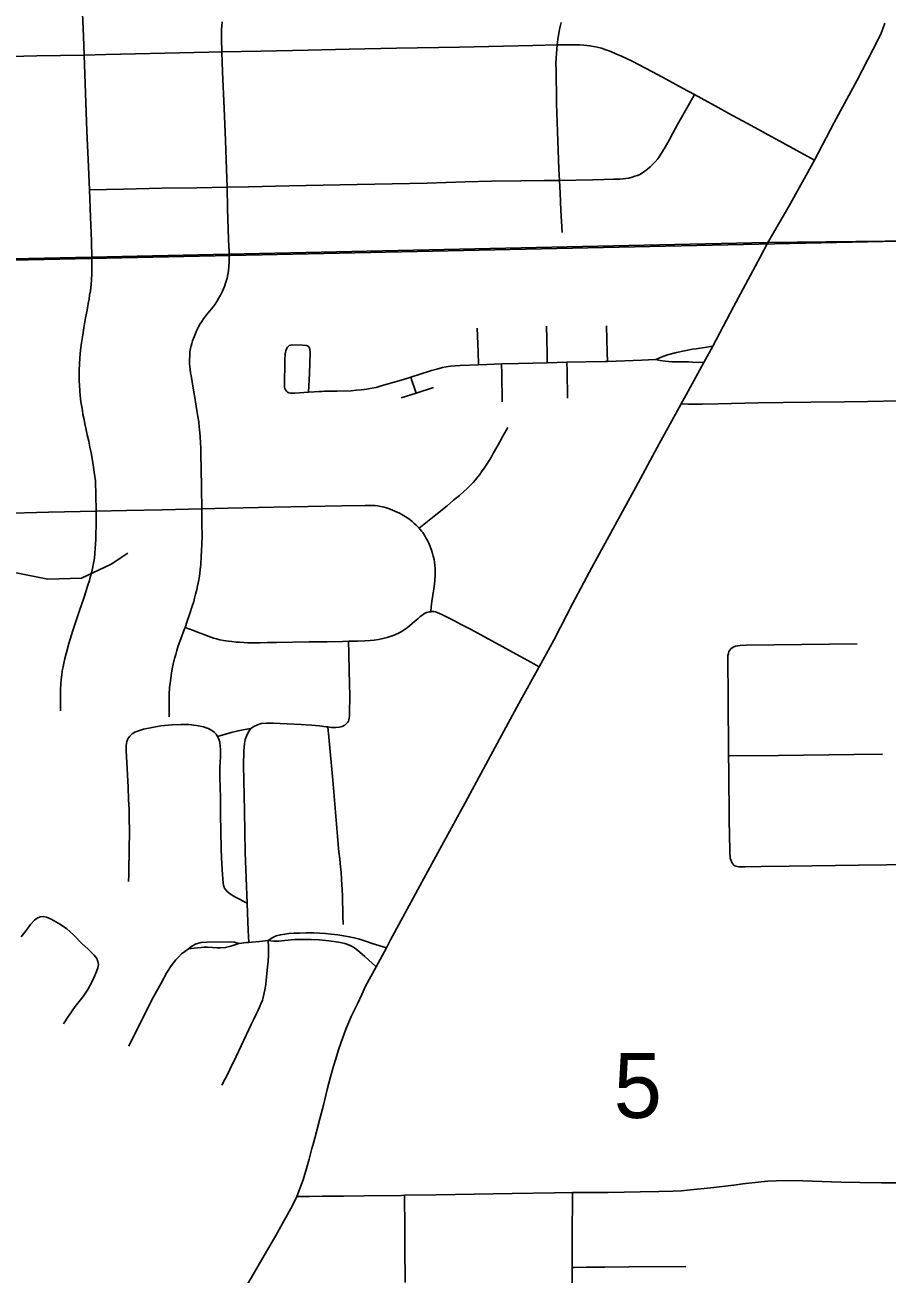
# Model space of a CAD drawing. Extents: x -6.4 to 34, y -4.2 to 22.
# Drawn here: x 4.993 to 5.548, y 15.21 to 16.015 of the extents above; entities that cross this region are included whole.
import ezdxf

# ---------------------------------------------------------------- set-up
doc = ezdxf.new("R2010")
doc.units = 0
for name, color, linetype in [('GM_X_City_Street', 7, 'Continuous'), ('GM_X_Corporation', 7, 'Continuous'), ('GM_X_County_Road', 7, 'Continuous'), ('GM_X_Minor_River', 7, 'Continuous'), ('GM_X_Section_Text', 7, 'Continuous'), ('GM_X_State_Route', 7, 'Continuous')]:
    doc.layers.add(name, color=color, linetype=linetype)

msp = doc.modelspace()

# ---------------------------------------------------------------- linework, layer by layer
at = {"layer": 'GM_X_City_Street'}
msp.add_line((5.24472, 15.77786), (5.25605, 15.78143), dxfattribs=at)
for points in [[(5.01565, 15.57307), (5.01549, 15.57751), (5.01549, 15.58072), (5.01566, 15.58713), (5.01582, 15.59025), (5.01607, 15.5933), (5.0164, 15.59634), (5.01674, 15.59889), (5.01723, 15.60144), (5.01773, 15.6039), (5.01838, 15.60686), (5.01937, 15.61073), (5.02103, 15.61641), (5.0235, 15.62479), (5.02754, 15.63704), (5.03075, 15.64633), (5.0333, 15.65414), (5.03422, 15.65708), (5.03479, 15.65916), (5.03555, 15.6621), (5.03619, 15.66492), (5.03693, 15.66829), (5.03743, 15.67158), (5.03776, 15.67462), (5.03801, 15.67766), (5.03818, 15.68071), (5.03826, 15.68358), (5.03834, 15.68605), (5.03851, 15.69329), (5.03852, 15.7017), (5.03852, 15.70447), (5.03844, 15.70982), (5.03828, 15.71467), (5.0382, 15.71837), (5.03804, 15.72125), (5.03779, 15.72405), (5.03739, 15.72693), (5.03693, 15.73017), (5.03645, 15.73283), (5.03591, 15.73581), (5.03525, 15.73926), (5.03452, 15.74305), (5.03378, 15.74691), (5.03288, 15.75103), (5.03196, 15.7552), (5.03137, 15.75797), (5.03074, 15.76081), (5.03009, 15.76411), (5.02968, 15.76657), (5.02927, 15.76896), (5.02878, 15.77217), (5.02829, 15.77636), (5.02805, 15.77932), (5.0278, 15.78294), (5.02764, 15.78557), (5.02764, 15.78853), (5.02769, 15.79252), (5.02791, 15.79652), (5.02814, 15.80054), (5.02856, 15.80556), (5.02913, 15.81024), (5.02988, 15.81543), (5.03062, 15.81995), (5.03169, 15.82636), (5.03268, 15.83138), (5.03351, 15.83558), (5.03401, 15.83845), (5.03438, 15.84091), (5.03483, 15.8438), (5.03533, 15.84782), (5.03554, 15.85089), (5.03575, 15.85481), (5.03583, 15.85893), (5.03575, 15.86477), (5.0356, 15.87587), (5.03503, 15.89125), (5.03433, 15.90873), (5.03373, 15.92356), (5.03251, 15.9466), (5.03171, 15.97103), (5.03079, 15.99559), (5.03034, 16.00788), (5.02928, 16.03246)], [(5.0856, 15.56931), (5.0856, 15.57252), (5.08557, 15.5768), (5.08553, 15.58058), (5.08561, 15.58371), (5.08586, 15.58823), (5.08619, 15.59102), (5.0866, 15.59415), (5.0871, 15.59736), (5.0876, 15.60024), (5.08826, 15.6032), (5.08908, 15.60673), (5.08982, 15.60952), (5.09056, 15.61199), (5.09145, 15.61491), (5.09304, 15.61956), (5.09551, 15.62589), (5.09585, 15.62684), (5.0973, 15.63088), (5.09905, 15.63576), (5.10054, 15.64045), (5.10144, 15.64349), (5.10204, 15.64579), (5.10268, 15.64826), (5.10343, 15.6513), (5.10395, 15.65366), (5.10449, 15.65648), (5.10515, 15.65985), (5.10565, 15.66405), (5.10599, 15.66766), (5.10631, 15.67227), (5.10648, 15.67638), (5.10665, 15.68017), (5.10682, 15.68617), (5.10674, 15.693), (5.10661, 15.70335), (5.10643, 15.71668), (5.10619, 15.72968), (5.10603, 15.73774), (5.10595, 15.74226), (5.10579, 15.74571), (5.10563, 15.74966), (5.10543, 15.75238), (5.10506, 15.75591), (5.10465, 15.75928), (5.10416, 15.76266), (5.10351, 15.7667), (5.10285, 15.7708), (5.10211, 15.77507), (5.10162, 15.77837), (5.10114, 15.78123), (5.10068, 15.78364), (5.10014, 15.78667), (5.09973, 15.78889), (5.09942, 15.79099), (5.09908, 15.79325), (5.09883, 15.79663), (5.09883, 15.79926), (5.09884, 15.80213), (5.099, 15.80452), (5.09934, 15.80658), (5.09975, 15.8083), (5.10017, 15.80973), (5.10073, 15.81159), (5.10164, 15.81406), (5.10255, 15.8162), (5.10354, 15.81841), (5.10461, 15.82047), (5.10568, 15.82237), (5.10664, 15.82389), (5.10782, 15.82573), (5.10979, 15.82836), (5.11185, 15.83091), (5.11391, 15.83338), (5.11523, 15.83518), (5.11638, 15.83691), (5.11745, 15.83872), (5.11869, 15.84086), (5.12, 15.84357), (5.12126, 15.84657), (5.12215, 15.84941), (5.12292, 15.852), (5.12346, 15.85434), (5.12387, 15.85665), (5.12412, 15.85952), (5.12421, 15.86216), (5.12424, 15.8668), (5.12422, 15.8689), (5.12397, 15.87688), (5.12325, 15.8967), (5.12297, 15.9105), (5.12261, 15.9222), (5.12196, 15.9407), (5.12115, 15.96143), (5.12002, 15.98462), (5.11959, 15.99774), (5.11951, 16.00018), (5.1194, 16.00379), (5.1193, 16.00757), (5.1193, 16.01011), (5.11938, 16.01209), (5.11954, 16.01447), (5.11987, 16.01702)], [(5.33883, 15.88123), (5.3381, 15.89571), (5.33756, 15.90657), (5.33715, 15.91492), (5.3368, 15.92211), (5.336, 15.94637), (5.33535, 15.96455), (5.33522, 15.97179), (5.33506, 15.98009), (5.33495, 15.98585), (5.33487, 15.99046), (5.33504, 15.99367), (5.33521, 15.99662), (5.33546, 15.99951), (5.33579, 16.00229), (5.33622, 16.00579), (5.33686, 16.00978), (5.33744, 16.01316), (5.33818, 16.01669)], [(4.97509, 15.99452), (5.00033, 15.99508), (5.03079, 15.99559), (5.04483, 15.99596), (5.07337, 15.99668), (5.11128, 15.99755), (5.11959, 15.99774), (5.14476, 15.99827), (5.17527, 15.99891), (5.20159, 15.99947), (5.23218, 16.00002), (5.27264, 16.00074), (5.31994, 16.00185), (5.33579, 16.00229), (5.34034, 16.00233), (5.34453, 16.00233), (5.3479, 16.00233), (5.35028, 16.00225), (5.35292, 16.00208), (5.35481, 16.00191), (5.35662, 16.00166), (5.35908, 16.00125), (5.36139, 16.00076), (5.36418, 16.00002), (5.36698, 15.99911), (5.37035, 15.99787), (5.37355, 15.99655), (5.37709, 15.99499), (5.38038, 15.99342), (5.38392, 15.9917), (5.38852, 15.9893), (5.39262, 15.98715), (5.39666, 15.98502), (5.40357, 15.98132), (5.41646, 15.97438), (5.42417, 15.97023), (5.43953, 15.96182), (5.44878, 15.95678), (5.45832, 15.95159), (5.48109, 15.93907), (5.50152, 15.92799)], [(5.03433, 15.90873), (5.05618, 15.90923), (5.08085, 15.90979), (5.10347, 15.9101), (5.12297, 15.9105), (5.13677, 15.91082), (5.16301, 15.91146), (5.20685, 15.91233), (5.25192, 15.91321), (5.27643, 15.91393), (5.29337, 15.91433), (5.31229, 15.91456), (5.32726, 15.9148), (5.33715, 15.91492), (5.35842, 15.91536), (5.36607, 15.91552), (5.37191, 15.9156), (5.37389, 15.91567), (5.37611, 15.91576), (5.37816, 15.91592), (5.37989, 15.91608), (5.38178, 15.91641), (5.384, 15.91698), (5.38581, 15.91756), (5.38738, 15.91813), (5.38886, 15.91879), (5.39067, 15.91978), (5.39223, 15.92076), (5.39396, 15.92208), (5.39569, 15.92356), (5.39741, 15.92528), (5.39881, 15.92676), (5.40046, 15.92882), (5.40194, 15.93079), (5.40367, 15.9335), (5.40532, 15.9363), (5.40789, 15.94089), (5.41026, 15.94534), (5.4133, 15.95093), (5.4166, 15.95693), (5.42002, 15.96294), (5.42417, 15.97023)], [(5.28492, 15.79608), (5.28467, 15.80436), (5.28423, 15.81959)], [(5.32932, 15.79737), (5.32925, 15.80307), (5.32907, 15.8127), (5.32891, 15.82097)], [(5.3681, 15.79829), (5.36796, 15.80392), (5.36756, 15.82128)], [(5.1755, 15.77849), (5.17614, 15.7904), (5.17637, 15.79704), (5.17644, 15.8043), (5.17633, 15.80596), (5.17611, 15.80703), (5.1757, 15.80772), (5.17511, 15.80816), (5.17404, 15.8085), (5.1715, 15.80873), (5.16485, 15.8089), (5.16383, 15.80879), (5.16293, 15.80848), (5.16226, 15.80797), (5.16186, 15.80748), (5.16145, 15.80673), (5.16107, 15.80581), (5.16085, 15.80506), (5.16067, 15.80418), (5.16044, 15.80315), (5.16029, 15.80195), (5.16019, 15.80067), (5.16013, 15.79913), (5.15986, 15.78236), (5.16003, 15.78158), (5.16027, 15.78086), (5.16065, 15.78005), (5.16127, 15.77904), (5.16196, 15.77844), (5.16275, 15.77807), (5.16377, 15.77784), (5.16469, 15.77786), (5.16668, 15.7779), (5.1755, 15.77849), (5.17909, 15.77873), (5.18216, 15.77888), (5.18391, 15.77896), (5.18584, 15.77904), (5.18755, 15.77906), (5.19399, 15.77911), (5.20294, 15.77935), (5.2062, 15.77966), (5.20967, 15.77998), (5.21295, 15.78048), (5.21632, 15.781), (5.21898, 15.78155), (5.2217, 15.78225), (5.23885, 15.78727), (5.24146, 15.7881), (5.25474, 15.79234), (5.25819, 15.79329), (5.26187, 15.7943), (5.26423, 15.79478), (5.26686, 15.79521), (5.26993, 15.79552), (5.27309, 15.79568), (5.28492, 15.79608), (5.29027, 15.79632), (5.29991, 15.79662), (5.3107, 15.79695), (5.32932, 15.79737), (5.34189, 15.79767), (5.36658, 15.79824), (5.3681, 15.79829), (5.39036, 15.79911), (5.39452, 15.79923), (5.39931, 15.7996)], [(5.39931, 15.7996), (5.40262, 15.80101), (5.40673, 15.80254), (5.41256, 15.80407), (5.4229, 15.8061), (5.42536, 15.80647), (5.43593, 15.80807)], [(5.39931, 15.7996), (5.40207, 15.79892), (5.40526, 15.79843), (5.40961, 15.79806), (5.42041, 15.79789), (5.42292, 15.79781), (5.43022, 15.79757)], [(5.30015, 15.7722), (5.29996, 15.79028), (5.29991, 15.79662)], [(5.34242, 15.77456), (5.34206, 15.79227), (5.34189, 15.79767)], [(5.23511, 15.77475), (5.24472, 15.77786), (5.2441, 15.77983), (5.24211, 15.78607), (5.24146, 15.7881)], [(5.41565, 15.77091), (5.42027, 15.77079), (5.42921, 15.77079), (5.43953, 15.77095), (5.46531, 15.77149), (5.48145, 15.77178), (5.49916, 15.77199), (5.52087, 15.77228), (5.53592, 15.77249), (5.55581, 15.77285), (5.56907, 15.77309), (5.58833, 15.77348), (5.60188, 15.77376), (5.61778, 15.77409), (5.65055, 15.77489), (5.66469, 15.77524), (5.68108, 15.77557)], [(5.24668, 15.69082), (5.24998, 15.69336), (5.25754, 15.69944), (5.26478, 15.70527), (5.26896, 15.70875), (5.27269, 15.71185), (5.27556, 15.7144), (5.27771, 15.71645), (5.28001, 15.71867), (5.28157, 15.72031), (5.28315, 15.72205), (5.28462, 15.72385), (5.28589, 15.72546), (5.28701, 15.72705), (5.28866, 15.72943), (5.29038, 15.73207), (5.29186, 15.73445), (5.29327, 15.73675), (5.29475, 15.7393), (5.2968, 15.743), (5.29842, 15.74597), (5.30067, 15.75007), (5.3038, 15.75566)], [(4.9768, 15.70032), (5.00788, 15.70104), (5.03852, 15.7017), (5.05805, 15.70216), (5.08108, 15.70272), (5.10661, 15.70335), (5.12335, 15.70376), (5.15305, 15.7044), (5.17517, 15.70488), (5.1968, 15.70527), (5.21193, 15.70542), (5.21449, 15.70546), (5.2167, 15.70542), (5.21835, 15.70534), (5.21981, 15.70516), (5.2209, 15.70501), (5.22213, 15.70476), (5.2241, 15.70426), (5.22567, 15.70385), (5.22697, 15.70342), (5.22813, 15.70303), (5.22953, 15.70245), (5.23109, 15.70176), (5.23249, 15.70114), (5.23397, 15.70039), (5.23553, 15.69957), (5.23767, 15.69833), (5.23948, 15.69718), (5.24096, 15.69611), (5.24219, 15.69512), (5.24359, 15.69389), (5.24482, 15.69274), (5.24597, 15.69159), (5.24668, 15.69082), (5.24734, 15.68999), (5.24816, 15.68891), (5.24901, 15.68796), (5.25008, 15.6864), (5.25115, 15.68459), (5.25213, 15.68278), (5.25293, 15.68109), (5.25383, 15.67896), (5.25468, 15.67661), (5.25534, 15.67447), (5.25583, 15.67283), (5.25632, 15.67069), (5.25665, 15.66888), (5.25681, 15.66707), (5.25697, 15.66485), (5.25705, 15.66246), (5.25697, 15.66033), (5.2568, 15.65761), (5.25656, 15.65481), (5.25614, 15.65169), (5.25556, 15.64766), (5.25498, 15.64355), (5.25449, 15.64017), (5.25416, 15.63693)], [(5.09585, 15.62684), (5.10062, 15.62504), (5.10563, 15.62314), (5.10924, 15.6218), (5.11188, 15.62084), (5.11443, 15.62001), (5.1162, 15.61951), (5.11838, 15.61894), (5.1206, 15.61844), (5.12208, 15.6182), (5.12389, 15.61795), (5.12611, 15.6177), (5.12874, 15.61745), (5.13097, 15.61731), (5.13384, 15.61712), (5.13614, 15.61703), (5.1395, 15.61692), (5.14428, 15.61695), (5.14897, 15.61705), (5.15473, 15.61719), (5.1757, 15.6175), (5.18746, 15.61766), (5.19741, 15.61782), (5.2012, 15.61791), (5.20695, 15.61805), (5.2118, 15.61821), (5.2151, 15.61838), (5.21765, 15.61862), (5.22044, 15.61904), (5.22341, 15.61969), (5.22603, 15.62043), (5.22877, 15.62132), (5.23053, 15.62194), (5.23184, 15.62251), (5.23341, 15.62325), (5.23509, 15.62412), (5.23706, 15.62527), (5.23895, 15.62658), (5.2406, 15.6279), (5.24216, 15.62931), (5.24369, 15.63064), (5.24583, 15.63246), (5.24743, 15.63382), (5.2485, 15.63464), (5.24957, 15.63538), (5.25055, 15.63595), (5.25154, 15.63637), (5.25261, 15.63669), (5.2535, 15.63689), (5.25416, 15.63693), (5.25483, 15.63702), (5.25623, 15.63702), (5.25719, 15.63689), (5.25845, 15.63653), (5.25993, 15.63587), (5.26174, 15.63504), (5.26478, 15.63356), (5.26906, 15.63134), (5.27389, 15.62883), (5.27983, 15.62574), (5.31871, 15.60449), (5.32416, 15.60151)], [(5.20195, 15.57189), (5.20197, 15.58264), (5.2016, 15.5989), (5.20133, 15.61027), (5.2012, 15.61791)], [(5.44765, 15.61298), (5.44921, 15.61408), (5.45056, 15.6147), (5.45205, 15.61506), (5.4537, 15.61524), (5.45748, 15.61533), (5.52896, 15.61627)], [(5.44765, 15.61298), (5.44643, 15.61139), (5.44605, 15.61015), (5.44577, 15.60873), (5.44565, 15.60699), (5.44562, 15.60531), (5.44583, 15.58301), (5.4462, 15.54402), (5.44629, 15.53456), (5.4466, 15.50276), (5.44694, 15.48325), (5.44706, 15.48083), (5.44714, 15.47933), (5.44728, 15.47824), (5.44756, 15.47705), (5.44799, 15.47593), (5.44855, 15.47501), (5.44893, 15.47444), (5.44958, 15.47375), (5.45024, 15.47332), (5.45094, 15.47301), (5.45173, 15.47278), (5.45285, 15.47265), (5.45677, 15.47268), (5.46719, 15.47274), (5.48518, 15.47294), (5.52985, 15.47357), (5.56605, 15.47407)], [(5.13703, 15.42389), (5.13664, 15.43157), (5.13606, 15.44289), (5.13581, 15.44926), (5.13454, 15.48181), (5.13407, 15.50854), (5.13346, 15.53837), (5.13364, 15.54711), (5.13411, 15.55208), (5.13467, 15.5547), (5.13546, 15.55685), (5.13674, 15.55962), (5.13825, 15.56163), (5.14012, 15.56307), (5.14245, 15.56419), (5.14486, 15.56488), (5.14832, 15.56514), (5.15255, 15.56514), (5.17076, 15.56424), (5.17385, 15.56412), (5.17756, 15.56388), (5.17992, 15.56366), (5.18253, 15.56342), (5.18674, 15.56287), (5.18796, 15.5627), (5.19033, 15.56247), (5.19303, 15.56235), (5.19531, 15.56252), (5.19718, 15.56305), (5.19876, 15.56387), (5.19999, 15.56486), (5.20058, 15.56558), (5.20114, 15.56636), (5.20151, 15.56724), (5.20174, 15.56849), (5.20184, 15.56988), (5.20195, 15.57189)], [(5.05945, 15.46311), (5.05961, 15.46746), (5.05971, 15.4705), (5.05999, 15.49593), (5.05989, 15.50347), (5.05981, 15.50955), (5.05952, 15.51607), (5.05917, 15.52401), (5.05881, 15.53188), (5.05782, 15.54748), (5.05792, 15.55073), (5.05844, 15.55331), (5.05903, 15.5551), (5.06031, 15.55684), (5.06182, 15.55819), (5.06352, 15.55929), (5.06658, 15.56049), (5.06914, 15.56131), (5.07458, 15.56243), (5.08028, 15.56337), (5.08757, 15.5641), (5.09323, 15.56439), (5.09829, 15.56423), (5.10332, 15.56366), (5.10773, 15.56283), (5.11084, 15.56181), (5.11258, 15.56092), (5.11472, 15.55936), (5.11593, 15.55817), (5.11678, 15.55662), (5.11757, 15.5548), (5.11818, 15.55298), (5.11859, 15.55045), (5.11866, 15.54815), (5.11874, 15.54595), (5.11862, 15.54341), (5.11846, 15.54003), (5.11833, 15.53709), (5.11819, 15.53415), (5.11825, 15.53149), (5.11832, 15.5286), (5.11851, 15.52562), (5.11851, 15.52237), (5.11864, 15.51863), (5.11876, 15.50619), (5.11893, 15.49556), (5.11919, 15.48437), (5.11943, 15.47814), (5.11954, 15.47503), (5.11978, 15.4707), (5.12035, 15.46214), (5.12062, 15.46069), (5.12131, 15.45891), (5.12256, 15.45706), (5.12428, 15.45553), (5.1264, 15.45403), (5.12839, 15.45302), (5.13581, 15.44926)], [(5.11678, 15.55662), (5.12557, 15.55908), (5.13001, 15.56032), (5.13433, 15.56101), (5.13825, 15.56163)], [(5.19779, 15.43535), (5.1976, 15.44122), (5.19723, 15.45373), (5.19711, 15.45796), (5.19672, 15.46443), (5.19644, 15.4691), (5.19607, 15.47266), (5.19556, 15.47756), (5.19507, 15.48222), (5.19458, 15.48698), (5.19413, 15.49242), (5.19119, 15.52838), (5.18858, 15.55616), (5.18796, 15.5627)], [(5.4462, 15.54402), (5.44728, 15.54404), (5.47831, 15.54441), (5.52692, 15.54502), (5.54538, 15.54524)], [(4.9903, 15.4275), (4.99348, 15.43167), (4.99629, 15.43537), (4.99886, 15.43832), (5.00052, 15.43952), (5.00245, 15.44034), (5.00455, 15.44056), (5.00658, 15.44019), (5.00962, 15.43893), (5.01563, 15.43552), (5.01976, 15.43257), (5.02391, 15.4287), (5.0296, 15.42303), (5.0333, 15.41976), (5.03736, 15.4157), (5.0389, 15.41352), (5.03968, 15.41167), (5.03999, 15.40963), (5.03971, 15.40756), (5.03878, 15.40508), (5.03781, 15.40252), (5.03604, 15.39877), (5.03327, 15.39354), (5.0301, 15.3891), (5.02764, 15.38583), (5.0251, 15.38257), (5.02065, 15.37631), (5.01748, 15.37151)], [(5.14952, 15.42509), (5.15246, 15.42708), (5.15461, 15.42811), (5.1573, 15.4288), (5.16023, 15.42921), (5.16283, 15.42957), (5.1661, 15.42976), (5.16964, 15.42996), (5.17387, 15.42998), (5.17895, 15.43), (5.18259, 15.42982), (5.18639, 15.42964), (5.19001, 15.42925), (5.19441, 15.42877), (5.19812, 15.42813), (5.20173, 15.42751), (5.20486, 15.42676), (5.20833, 15.42593), (5.21272, 15.42452), (5.21653, 15.4233), (5.2256, 15.4204)], [(5.09806, 15.41969), (5.10021, 15.42141), (5.10305, 15.42302), (5.10626, 15.42383), (5.1098, 15.42408), (5.12491, 15.42435), (5.12767, 15.42407), (5.13052, 15.42329)], [(5.09806, 15.41969), (5.10177, 15.42012), (5.10393, 15.42041), (5.10617, 15.42072), (5.10824, 15.42081), (5.11029, 15.42081), (5.11352, 15.42062), (5.11631, 15.42045), (5.11878, 15.42036), (5.12197, 15.42062), (5.12543, 15.4214), (5.12785, 15.42226), (5.13052, 15.42329)], [(5.11964, 15.33184), (5.12399, 15.34049), (5.12547, 15.34344), (5.12703, 15.3467), (5.1338, 15.36081), (5.13846, 15.37098), (5.13995, 15.374), (5.14175, 15.37768), (5.14296, 15.38014), (5.14393, 15.38213), (5.14496, 15.38475), (5.14573, 15.38671), (5.14672, 15.39025), (5.14752, 15.39447), (5.14784, 15.39704), (5.14816, 15.39962), (5.14866, 15.40371), (5.14903, 15.40809), (5.14934, 15.41189), (5.14969, 15.41594), (5.14969, 15.42095), (5.14952, 15.42509)], [(5.13052, 15.42329), (5.13553, 15.42375), (5.13703, 15.42389), (5.13898, 15.42406), (5.14382, 15.42453), (5.14952, 15.42509)], [(5.14952, 15.42509), (5.1528, 15.42475), (5.15634, 15.42477), (5.16021, 15.4252), (5.16636, 15.4257), (5.16981, 15.42577), (5.17316, 15.42584), (5.17714, 15.42568), (5.18243, 15.42546), (5.18861, 15.42496), (5.19472, 15.4241), (5.19692, 15.42363), (5.19892, 15.42314), (5.20181, 15.4221), (5.20358, 15.42116), (5.20504, 15.42034), (5.20846, 15.41772), (5.21166, 15.41485), (5.21903, 15.40825)], [(5.05958, 15.3571), (5.07472, 15.38739), (5.08019, 15.39717), (5.08406, 15.40441), (5.087, 15.40881), (5.08841, 15.41075), (5.08985, 15.4127), (5.09159, 15.41449), (5.09356, 15.41649), (5.09563, 15.41813), (5.09806, 15.41969)], [(5.23769, 15.20482), (5.23761, 15.22815), (5.23755, 15.24234), (5.23733, 15.25826), (5.23729, 15.26095)], [(5.34528, 15.16717), (5.34538, 15.21444), (5.34542, 15.23373), (5.34551, 15.26162), (5.34552, 15.26274)], [(5.34538, 15.21444), (5.34659, 15.21446), (5.3545, 15.21455), (5.36649, 15.21465), (5.38194, 15.21477), (5.41861, 15.21507)]]:
    msp.add_lwpolyline(points, dxfattribs=at)
at = {"layer": 'GM_X_Corporation'}
for points in [[(6.5599, 15.89325), (5.71845, 15.87759), (5.47098, 15.8749), (5.12404, 15.86735), (5.03555, 15.86533), (4.94435, 15.86353)], [(4.94435, 15.86353), (5.03555, 15.86533), (5.12404, 15.86735), (5.47098, 15.8749), (5.71845, 15.87759), (6.5599, 15.89325)]]:
    msp.add_lwpolyline(points, dxfattribs=at)
msp.add_lwpolyline([(4.92466, 15.86229), (5.93632, 15.88385), (5.96639, 14.68043), (5.96322, 14.68037), (4.84426, 14.65545), (4.82849, 15.2133), (4.81021, 15.86007)], close=True, dxfattribs=at)
at = {"layer": 'GM_X_County_Road'}
for points in [[(5.45537, 15.26828), (5.46711, 15.26966), (5.4715, 15.27004), (5.47681, 15.27031), (5.48325, 15.2704), (5.49407, 15.2702), (5.5188, 15.26948), (5.531, 15.26915), (5.54471, 15.26896), (5.56392, 15.26895), (5.58896, 15.26916), (5.62757, 15.26979), (5.65918, 15.2705), (5.67847, 15.27086), (5.69341, 15.27114), (5.74079, 15.27199), (5.80272, 15.27309), (5.87556, 15.27445), (5.91357, 15.27516), (5.92068, 15.27533), (5.92927, 15.27555), (5.93384, 15.27573)], [(5.16781, 15.26024), (5.17612, 15.26019), (5.18438, 15.2603), (5.19801, 15.26036), (5.21107, 15.26055), (5.23531, 15.26092), (5.23729, 15.26095), (5.25767, 15.26126), (5.30675, 15.26211), (5.33398, 15.26259), (5.34552, 15.26274), (5.36853, 15.26283), (5.38924, 15.2631), (5.40117, 15.26337), (5.41044, 15.26364), (5.41573, 15.26392), (5.4216, 15.26438), (5.43463, 15.26583), (5.44949, 15.26758), (5.45537, 15.26828)]]:
    msp.add_lwpolyline(points, dxfattribs=at)
at = {"layer": 'GM_X_Minor_River'}
msp.add_lwpolyline([(4.79425, 15.59885), (4.80336, 15.59871), (4.83033, 15.63075), (4.8497, 15.6285), (4.86948, 15.62475), (4.88982, 15.63012), (4.90911, 15.63167), (4.92822, 15.64157), (4.94913, 15.65644), (4.96908, 15.66255), (4.98804, 15.66182), (5.00743, 15.65806), (5.02902, 15.65852), (5.04815, 15.66766), (5.05899, 15.67472)], dxfattribs=at)
at = {"layer": 'GM_X_State_Route'}
for points in [[(5.17816, 15.293), (5.17948, 15.29777), (5.18282, 15.31013), (5.18505, 15.31903), (5.18753, 15.32904), (5.18965, 15.33727), (5.1915, 15.34412), (5.19299, 15.34881), (5.19485, 15.35462), (5.19658, 15.35957), (5.19923, 15.36731), (5.20294, 15.37611), (5.20691, 15.38439), (5.20972, 15.39038), (5.21218, 15.39561), (5.21561, 15.40195), (5.21903, 15.40825), (5.2256, 15.4204), (5.22835, 15.42547), (5.24033, 15.44769), (5.24711, 15.46025), (5.26125, 15.48641), (5.27647, 15.51394), (5.29569, 15.54981), (5.31101, 15.5778), (5.32416, 15.60151), (5.33355, 15.61871), (5.34582, 15.64241), (5.35808, 15.66546), (5.3863, 15.71729), (5.40004, 15.74269), (5.41565, 15.77091), (5.41883, 15.77665), (5.43022, 15.79757), (5.43593, 15.80807), (5.44934, 15.83333), (5.46647, 15.8655), (5.47118, 15.87435), (5.48613, 15.89999), (5.50152, 15.92799), (5.51429, 15.95215), (5.52897, 15.97947), (5.5428, 16.0062), (5.54445, 16.00973), (5.54577, 16.0131), (5.54683, 16.01623)], [(5.12586, 15.18577), (5.14298, 15.21553), (5.15443, 15.23502), (5.16507, 15.25438), (5.16781, 15.26024), (5.17204, 15.27093), (5.17408, 15.27826), (5.17576, 15.28429), (5.17764, 15.29109), (5.17816, 15.293)]]:
    msp.add_lwpolyline(points, dxfattribs=at)

# ---------------------------------------------------------------- texts
at = {"layer": 'GM_X_Section_Text'}
msp.add_text('5', height=0.04186, rotation=0.00001, dxfattribs=at).set_placement((5.37208, 15.31079))

doc.saveas('drawing.dxf')
